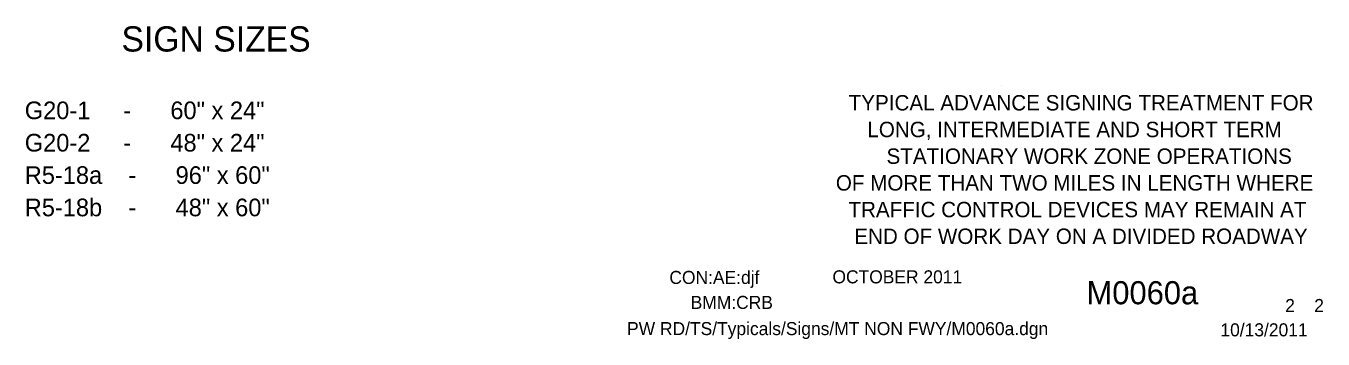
# Model space of a CAD drawing. Extents: x 19023 to 20762, y 4888 to 6104.
# Drawn here: x 20092 to 20709, y 5121 to 5270 of the extents above; entities that cross this region are included whole.
import ezdxf

# ---------------------------------------------------------------- set-up
doc = ezdxf.new("R2010")
doc.units = 0
for name, color, linetype in [('BORDER', 7, 'Continuous'), ('BORDER_SIGNAL_WO', 7, 'Continuous'), ('TYPICAL_TEXT_DIMEN_PR', 7, 'Continuous')]:
    doc.layers.add(name, color=color, linetype=linetype)

msp = doc.modelspace()

# ---------------------------------------------------------------- linework, layer by layer
at = {"layer": 'BORDER'}
for p, q in [((20555.753, 5241.887), (20555.753, 5241.887)), ((20555.753, 5241.887), (20555.753, 5241.887)), ((20596.417, 5194.208), (20596.417, 5194.208)), ((20596.417, 5194.208), (20596.417, 5194.208)), ((20596.417, 5194.208), (20596.417, 5194.208)), ((20596.417, 5194.208), (20596.417, 5194.208))]:
    msp.add_line(p, q, dxfattribs=at)

# ---------------------------------------------------------------- texts
at = {"layer": 'BORDER_SIGNAL_WO'}
for s, height, p in [('TYPICAL ADVANCE SIGNING TREATMENT FOR', 7.33372, (20483.185, 5229.791)), ('LONG, INTERMEDIATE AND SHORT TERM ', 7.33372, (20492.075, 5217.091)), ('STATIONARY WORK ZONE OPERATIONS', 7.33372, (20501.191, 5204.391)), ('OF MORE THAN TWO MILES IN LENGTH WHERE ', 7.33372, (20477.076, 5191.691)), ('TRAFFIC CONTROL DEVICES MAY REMAIN AT', 7.33372, (20483.075, 5178.991)), (' END OF WORK DAY ON A DIVIDED ROADWAY', 7.33372, (20483.139, 5166.29)), ('CON:AE:djf', 6.2, (20397.854, 5147.266)), ('    OCTOBER 2011    ', 6.2, (20466.248, 5147.547)), ('    M0060a   ', 11, (20580.029, 5137.588)), ('BMM:CRB   ', 6.2, (20407.977, 5135.382)), (' 2    2 ', 6.2, (20688.613, 5133.906)), ('PW RD/TS/Typicals/Signs/MT NON FWY/M0060a.dgn  ', 6.2, (20377.721, 5122.919)), ('10/13/2011    ', 6.19999, (20660.095, 5122.338))]:
    msp.add_text(s, height=height, dxfattribs=at).set_placement(p)
at = {"layer": 'TYPICAL_TEXT_DIMEN_PR'}
for s, height, p in [('SIGN SIZES', 12, (20137.109, 5257.831)), ('G20-1     -      60" x 24"', 8.4, (20091.089, 5225.659)), ('G20-2     -      48" x 24"', 8.4, (20091.089, 5210.259)), ('R5-18a    -      96" x 60"', 8.4, (20091.089, 5194.859)), ('R5-18b    -      48" x 60"', 8.4, (20091.089, 5179.459))]:
    msp.add_text(s, height=height, dxfattribs=at).set_placement(p)

doc.saveas('drawing.dxf')
